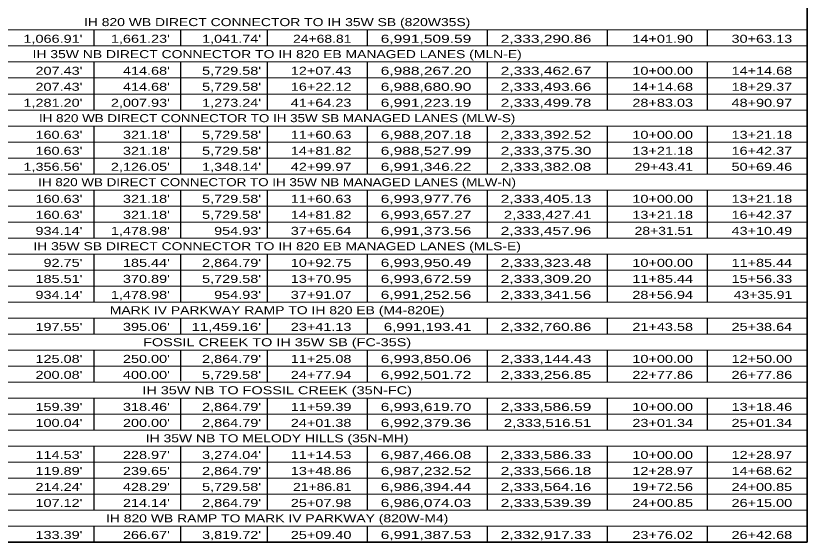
# Model space of a CAD drawing. Extents: x 1953053 to 1967065, y 7363860 to 7371201.
# Drawn here: x 1954423 to 1955610, y 7367776 to 7368565 of the extents above; entities that cross this region are included whole.
import ezdxf
from ezdxf.enums import TextEntityAlignment as Align

# ---------------------------------------------------------------- set-up
doc = ezdxf.new("R2010")
doc.units = 0
doc.header["$LTSCALE"] = 4.8
doc.layers.add('10', color=7, linetype='Continuous')
doc.layers.add('12', color=7, linetype='Continuous', lineweight=25)

msp = doc.modelspace()

# ---------------------------------------------------------------- linework, layer by layer
at = {"layer": '12', "lineweight": 35}
for p, q in [((1955609.815, 7367775.748), (1955609.815, 7370055.746)), ((1953886.483, 7367775.748), (1955609.815, 7367775.748))]:
    msp.add_line(p, q, dxfattribs=at)
at = {"layer": '12', "lineweight": 13}
for p, q in [((1953886.483, 7368543.748), (1955609.815, 7368543.748)), ((1953886.483, 7368519.748), (1955609.815, 7368519.748)), ((1953886.483, 7368495.748), (1955609.815, 7368495.748)), ((1953886.483, 7368471.748), (1955609.815, 7368471.748)), ((1953886.483, 7368447.748), (1955609.815, 7368447.748)), ((1953886.483, 7368423.748), (1955609.815, 7368423.748)), ((1953886.483, 7368399.748), (1955609.815, 7368399.748)), ((1953886.483, 7368375.748), (1955609.815, 7368375.748)), ((1953886.483, 7368351.748), (1955609.815, 7368351.748)), ((1953886.483, 7368327.748), (1955609.815, 7368327.748)), ((1953886.483, 7368303.748), (1955609.815, 7368303.748)), ((1953886.483, 7368279.748), (1955609.815, 7368279.748)), ((1953886.483, 7368255.748), (1955609.815, 7368255.748)), ((1953886.483, 7368231.748), (1955609.815, 7368231.748)), ((1953886.483, 7368207.748), (1955609.815, 7368207.748)), ((1953886.483, 7368183.748), (1955609.815, 7368183.748)), ((1953886.483, 7368159.748), (1955609.815, 7368159.748)), ((1953886.483, 7368135.748), (1955609.815, 7368135.748)), ((1953886.483, 7368111.748), (1955609.815, 7368111.748)), ((1953886.483, 7368087.748), (1955609.815, 7368087.748)), ((1953886.483, 7368063.748), (1955609.815, 7368063.748)), ((1953886.483, 7368039.748), (1955609.815, 7368039.748)), ((1953886.483, 7368015.748), (1955609.815, 7368015.748)), ((1953886.483, 7367991.748), (1955609.815, 7367991.748)), ((1953886.483, 7367967.748), (1955609.815, 7367967.748)), ((1953886.483, 7367943.748), (1955609.815, 7367943.748)), ((1953886.483, 7367919.748), (1955609.815, 7367919.748)), ((1953886.483, 7367895.748), (1955609.815, 7367895.748)), ((1953886.483, 7367871.748), (1955609.815, 7367871.748)), ((1953886.483, 7367847.748), (1955609.815, 7367847.748)), ((1953886.483, 7367823.748), (1955609.815, 7367823.748)), ((1953886.483, 7367823.748), (1955609.815, 7367823.748)), ((1953886.483, 7367799.748), (1955609.815, 7367799.748))]:
    msp.add_line(p, q, dxfattribs=at)
at = {"layer": '12'}
for p, q in [((1954539.815, 7368543.748), (1954539.815, 7368519.748)), ((1954669.815, 7368543.748), (1954669.815, 7368519.748)), ((1954799.815, 7368543.748), (1954799.815, 7368519.748)), ((1954949.815, 7368543.748), (1954949.815, 7368519.748)), ((1955129.815, 7368543.748), (1955129.815, 7368519.748)), ((1955309.815, 7368543.748), (1955309.815, 7368519.748)), ((1955459.815, 7368543.748), (1955459.815, 7368519.748)), ((1954539.815, 7368495.748), (1954539.815, 7368423.748)), ((1954669.815, 7368495.748), (1954669.815, 7368423.748)), ((1954799.815, 7368495.748), (1954799.815, 7368423.748)), ((1954949.815, 7368495.748), (1954949.815, 7368423.748)), ((1955129.815, 7368495.748), (1955129.815, 7368423.748)), ((1955309.815, 7368495.748), (1955309.815, 7368423.748)), ((1955459.815, 7368495.748), (1955459.815, 7368423.748)), ((1954539.815, 7368399.748), (1954539.815, 7368327.748)), ((1954669.815, 7368399.748), (1954669.815, 7368327.748)), ((1954799.815, 7368399.748), (1954799.815, 7368327.748)), ((1954949.815, 7368399.748), (1954949.815, 7368327.748)), ((1955129.815, 7368399.748), (1955129.815, 7368327.748)), ((1955309.815, 7368399.748), (1955309.815, 7368327.748)), ((1955459.815, 7368399.748), (1955459.815, 7368327.748)), ((1954539.815, 7368303.748), (1954539.815, 7368231.748)), ((1954669.815, 7368303.748), (1954669.815, 7368231.748)), ((1954799.815, 7368303.748), (1954799.815, 7368231.748)), ((1954949.815, 7368303.748), (1954949.815, 7368231.748)), ((1955129.815, 7368303.748), (1955129.815, 7368231.748)), ((1955309.815, 7368303.748), (1955309.815, 7368231.748)), ((1955459.815, 7368303.748), (1955459.815, 7368231.748)), ((1954539.815, 7368207.748), (1954539.815, 7368135.748)), ((1954669.815, 7368207.748), (1954669.815, 7368135.748)), ((1954799.815, 7368207.748), (1954799.815, 7368135.748)), ((1954949.815, 7368207.748), (1954949.815, 7368135.748)), ((1955129.815, 7368207.748), (1955129.815, 7368135.748)), ((1955309.815, 7368207.748), (1955309.815, 7368135.748)), ((1955459.815, 7368207.748), (1955459.815, 7368135.748)), ((1954539.815, 7368111.748), (1954539.815, 7368087.748)), ((1954669.815, 7368111.748), (1954669.815, 7368087.748)), ((1954799.815, 7368111.748), (1954799.815, 7368087.748)), ((1954949.815, 7368111.748), (1954949.815, 7368087.748)), ((1955129.815, 7368111.748), (1955129.815, 7368087.748)), ((1955309.815, 7368111.748), (1955309.815, 7368087.748)), ((1955459.815, 7368111.748), (1955459.815, 7368087.748)), ((1954539.815, 7368063.748), (1954539.815, 7368015.748)), ((1954669.815, 7368063.748), (1954669.815, 7368017.838)), ((1954799.815, 7368063.748), (1954799.815, 7368015.748)), ((1954949.815, 7368063.748), (1954949.815, 7368015.748)), ((1955129.815, 7368063.748), (1955129.815, 7368015.748)), ((1955309.815, 7368063.748), (1955309.815, 7368015.748)), ((1955459.815, 7368063.748), (1955459.815, 7368015.748)), ((1954539.815, 7367991.748), (1954539.815, 7367943.748)), ((1954669.815, 7367991.748), (1954669.815, 7367943.748)), ((1954799.815, 7367991.748), (1954799.815, 7367943.748)), ((1954949.815, 7367991.748), (1954949.815, 7367943.748)), ((1955129.815, 7367991.748), (1955129.815, 7367943.748)), ((1955309.815, 7367991.748), (1955309.815, 7367943.748)), ((1955459.815, 7367991.748), (1955459.815, 7367943.748)), ((1954539.815, 7367919.748), (1954539.815, 7367823.748)), ((1954669.815, 7367919.748), (1954669.815, 7367823.748)), ((1954799.815, 7367919.748), (1954799.815, 7367823.748)), ((1954949.815, 7367919.748), (1954949.815, 7367823.748)), ((1955129.815, 7367919.748), (1955129.815, 7367823.748)), ((1955309.815, 7367919.748), (1955309.815, 7367823.748)), ((1955459.815, 7367919.748), (1955459.815, 7367823.748)), ((1954539.815, 7367799.748), (1954539.815, 7367775.748)), ((1954669.815, 7367799.748), (1954669.815, 7367775.748)), ((1954799.815, 7367799.748), (1954799.815, 7367775.748)), ((1954949.815, 7367799.748), (1954949.815, 7367775.748)), ((1955129.815, 7367799.748), (1955129.815, 7367775.748)), ((1955309.815, 7367799.748), (1955309.815, 7367775.748)), ((1955459.815, 7367799.748), (1955459.815, 7367775.748))]:
    msp.add_line(p, q, dxfattribs=at)

# ---------------------------------------------------------------- texts
at = {"layer": '10'}
for s, width, p in [('IH 820 WB DIRECT CONNECTOR TO IH 35W SB (820W35S)', 1.3, (1954814.815, 7368549.542)), ('IH 35W NB DIRECT CONNECTOR TO IH 820 EB MANAGED LANES (MLN-E)', 1.3, (1954814.816, 7368501.542)), ('IH 820 WB DIRECT CONNECTOR TO IH 35W SB MANAGED LANES (MLW-S)', 1.25, (1954814.816, 7368405.542)), ('IH 820 WB DIRECT CONNECTOR TO IH 35W NB MANAGED LANES (MLW-N)', 1.25, (1954814.816, 7368309.542)), ('IH 35W SB DIRECT CONNECTOR TO IH 820 EB MANAGED LANES (MLS-E)', 1.3, (1954814.816, 7368213.542)), ('MARK IV PARKWAY RAMP TO IH 820 EB (M4-820E)', 1.3, (1954814.815, 7368117.542)), ('FOSSIL CREEK TO IH 35W SB (FC-35S)', 1.35, (1954814.815, 7368069.542)), ('IH 35W NB TO FOSSIL CREEK (35N-FC)', 1.35, (1954814.815, 7367997.542)), ('IH 35W NB TO MELODY HILLS (35N-MH)', 1.3, (1954814.815, 7367925.542)), ('IH 820 WB RAMP TO MARK IV PARKWAY (820W-M4)', 1.3, (1954814.815, 7367805.542))]:
    msp.add_text(s, height=12, dxfattribs=dict(at, width=width)).set_placement(p, align=Align.CENTER)
for s, width, p in [("1,066.91'", 1.35, (1954522.742, 7368524.575)), ("1,661.23'", 1.35, (1954653.939, 7368524.575)), ("1,041.74'", 1.35, (1954790.708, 7368524.575)), ('24+68.81', 1.3, (1954926.252, 7368524.575)), ('6,991,509.59', 1.45, (1955106.017, 7368524.575)), ('2,333,290.86', 1.45, (1955286.017, 7368524.575)), ('14+01.90', 1.35, (1955438.595, 7368524.575)), ('30+63.13', 1.35, (1955587.327, 7368524.575)), ("207.43'", 1.35, (1954522.742, 7368476.577)), ("414.68'", 1.35, (1954653.939, 7368476.577)), ("5,729.58'", 1.35, (1954790.708, 7368476.577)), ('12+07.43', 1.35, (1954926.252, 7368476.577)), ('6,988,267.20', 1.45, (1955106.017, 7368476.577)), ('2,333,462.67', 1.45, (1955286.017, 7368476.577)), ('10+00.00', 1.35, (1955438.595, 7368476.577)), ('14+14.68', 1.35, (1955587.327, 7368476.577)), ("207.43'", 1.35, (1954522.742, 7368452.577)), ("414.68'", 1.35, (1954653.939, 7368452.577)), ("5,729.58'", 1.35, (1954790.708, 7368452.577)), ('16+22.12', 1.35, (1954926.252, 7368452.577)), ('6,988,680.90', 1.45, (1955106.017, 7368452.577)), ('2,333,493.66', 1.45, (1955286.017, 7368452.577)), ('14+14.68', 1.35, (1955438.595, 7368452.577)), ('18+29.37', 1.35, (1955587.327, 7368452.577)), ("1,281.20'", 1.35, (1954522.742, 7368428.577)), ("2,007.93'", 1.35, (1954653.939, 7368428.577)), ("1,273.24'", 1.35, (1954790.708, 7368428.577)), ('41+64.23', 1.35, (1954926.252, 7368428.577)), ('6,991,223.19', 1.45, (1955106.017, 7368428.577)), ('2,333,499.78', 1.45, (1955286.017, 7368428.577)), ('28+83.03', 1.35, (1955438.595, 7368428.577)), ('48+90.97', 1.35, (1955587.327, 7368428.577)), ("160.63'", 1.35, (1954522.742, 7368380.575)), ("321.18'", 1.35, (1954653.939, 7368380.575)), ("5,729.58'", 1.35, (1954790.708, 7368380.575)), ('11+60.63', 1.35, (1954926.252, 7368380.575)), ('6,988,207.18', 1.45, (1955106.017, 7368380.575)), ('2,333,392.52', 1.45, (1955286.017, 7368380.575)), ('10+00.00', 1.35, (1955438.595, 7368380.575)), ('13+21.18', 1.35, (1955587.327, 7368380.575)), ("160.63'", 1.35, (1954522.742, 7368356.575)), ("321.18'", 1.35, (1954653.939, 7368356.575)), ("5,729.58'", 1.35, (1954790.708, 7368356.575)), ('14+81.82', 1.35, (1954926.252, 7368356.575)), ('6,988,527.99', 1.45, (1955106.017, 7368356.575)), ('2,333,375.30', 1.45, (1955286.017, 7368356.575)), ('13+21.18', 1.35, (1955438.595, 7368356.575)), ('16+42.37', 1.35, (1955587.327, 7368356.575)), ("1,356.56'", 1.35, (1954522.742, 7368332.577)), ("2,126.05'", 1.35, (1954653.939, 7368332.577)), ("1,348.14'", 1.35, (1954790.708, 7368332.577)), ('42+99.97', 1.35, (1954926.252, 7368332.577)), ('6,991,346.22', 1.45, (1955106.017, 7368332.577)), ('2,333,382.08', 1.45, (1955286.017, 7368332.577)), ('29+43.41', 1.3, (1955438.595, 7368332.577)), ('50+69.46', 1.35, (1955587.327, 7368332.577)), ("160.63'", 1.35, (1954522.742, 7368284.577)), ("321.18'", 1.35, (1954653.939, 7368284.577)), ("5,729.58'", 1.35, (1954790.708, 7368284.577)), ('11+60.63', 1.35, (1954926.252, 7368284.577)), ('6,993,977.76', 1.45, (1955106.017, 7368284.577)), ('2,333,405.13', 1.45, (1955286.017, 7368284.577)), ('10+00.00', 1.35, (1955438.595, 7368284.577)), ('13+21.18', 1.35, (1955587.327, 7368284.577)), ("160.63'", 1.35, (1954522.742, 7368260.577)), ("321.18'", 1.35, (1954653.939, 7368260.577)), ("5,729.58'", 1.35, (1954790.708, 7368260.577)), ('14+81.82', 1.35, (1954926.252, 7368260.577)), ('6,993,657.27', 1.45, (1955106.017, 7368260.577)), ('2,333,427.41', 1.4, (1955286.017, 7368260.577)), ('13+21.18', 1.35, (1955438.595, 7368260.577)), ('16+42.37', 1.35, (1955587.327, 7368260.577)), ("934.14'", 1.35, (1954522.742, 7368236.577)), ("1,478.98'", 1.35, (1954653.939, 7368236.577)), ("954.93'", 1.35, (1954790.708, 7368236.577)), ('37+65.64', 1.35, (1954926.252, 7368236.577)), ('6,991,373.56', 1.45, (1955106.017, 7368236.577)), ('2,333,457.96', 1.45, (1955286.017, 7368236.577)), ('28+31.51', 1.3, (1955438.595, 7368236.577)), ('43+10.49', 1.35, (1955587.327, 7368236.577)), ("92.75'", 1.35, (1954522.742, 7368188.577)), ("185.44'", 1.35, (1954653.939, 7368188.577)), ("2,864.79'", 1.35, (1954790.708, 7368188.577)), ('10+92.75', 1.35, (1954926.252, 7368188.577)), ('6,993,950.49', 1.45, (1955106.017, 7368188.577)), ('2,333,323.48', 1.45, (1955286.017, 7368188.577)), ('10+00.00', 1.35, (1955438.595, 7368188.577)), ('11+85.44', 1.35, (1955587.327, 7368188.577)), ("185.51'", 1.35, (1954522.742, 7368164.577)), ("370.89'", 1.35, (1954653.939, 7368164.577)), ("5,729.58'", 1.35, (1954790.708, 7368164.577)), ('13+70.95', 1.35, (1954926.252, 7368164.577)), ('6,993,672.59', 1.45, (1955106.017, 7368164.577)), ('2,333,309.20', 1.45, (1955286.017, 7368164.577)), ('11+85.44', 1.35, (1955438.595, 7368164.577)), ('15+56.33', 1.35, (1955587.327, 7368164.577)), ("934.14'", 1.35, (1954522.742, 7368140.577)), ("1,478.98'", 1.35, (1954653.939, 7368140.577)), ("954.93'", 1.35, (1954790.708, 7368140.577)), ('37+91.07', 1.35, (1954926.252, 7368140.577)), ('6,991,252.56', 1.45, (1955106.017, 7368140.577)), ('2,333,341.56', 1.45, (1955286.017, 7368140.577)), ('28+56.94', 1.35, (1955438.595, 7368140.577)), ('43+35.91', 1.3, (1955587.327, 7368140.577)), ("197.55'", 1.35, (1954522.742, 7368092.577)), ("395.06'", 1.35, (1954653.939, 7368092.577)), ("11,459.16'", 1.4, (1954790.708, 7368092.577)), ('23+41.13', 1.35, (1954926.252, 7368092.577)), ('6,991,193.41', 1.4, (1955106.017, 7368092.577)), ('2,332,760.86', 1.45, (1955286.017, 7368092.577)), ('21+43.58', 1.35, (1955438.595, 7368092.577)), ('25+38.64', 1.35, (1955587.327, 7368092.577)), ("125.08'", 1.35, (1954522.742, 7368044.577)), ("250.00'", 1.35, (1954653.939, 7368044.577)), ("2,864.79'", 1.35, (1954790.708, 7368044.577)), ('11+25.08', 1.35, (1954926.252, 7368044.577)), ('6,993,850.06', 1.45, (1955106.017, 7368044.577)), ('2,333,144.43', 1.45, (1955286.017, 7368044.577)), ('10+00.00', 1.35, (1955438.595, 7368044.577)), ('12+50.00', 1.35, (1955587.327, 7368044.577)), ("200.08'", 1.35, (1954522.742, 7368020.577)), ("400.00'", 1.35, (1954653.939, 7368020.577)), ("5,729.58'", 1.35, (1954790.708, 7368020.577)), ('24+77.94', 1.35, (1954926.252, 7368020.577)), ('6,992,501.72', 1.45, (1955106.017, 7368020.577)), ('2,333,256.85', 1.45, (1955286.017, 7368020.577)), ('22+77.86', 1.35, (1955438.595, 7368020.577)), ('26+77.86', 1.35, (1955587.327, 7368020.577)), ("159.39'", 1.35, (1954522.742, 7367972.577)), ("318.46'", 1.35, (1954653.939, 7367972.577)), ("2,864.79'", 1.35, (1954790.708, 7367972.577)), ('11+59.39', 1.35, (1954926.252, 7367972.577)), ('6,993,619.70', 1.45, (1955106.017, 7367972.577)), ('2,333,586.59', 1.45, (1955286.017, 7367972.577)), ('10+00.00', 1.35, (1955438.595, 7367972.577)), ('13+18.46', 1.35, (1955587.327, 7367972.577)), ("100.04'", 1.35, (1954522.742, 7367948.577)), ("200.00'", 1.35, (1954653.939, 7367948.577)), ("2,864.79'", 1.35, (1954790.708, 7367948.577)), ('24+01.38', 1.35, (1954926.252, 7367948.577)), ('6,992,379.36', 1.45, (1955106.017, 7367948.577)), ('2,333,516.51', 1.4, (1955286.017, 7367948.577)), ('23+01.34', 1.35, (1955438.595, 7367948.577)), ('25+01.34', 1.35, (1955587.327, 7367948.577)), ("114.53'", 1.35, (1954522.742, 7367900.575)), ("228.97'", 1.35, (1954653.939, 7367900.575)), ("3,274.04'", 1.35, (1954790.708, 7367900.575)), ('11+14.53', 1.35, (1954926.252, 7367900.575)), ('6,987,466.08', 1.45, (1955106.017, 7367900.575)), ('2,333,586.33', 1.45, (1955286.017, 7367900.575)), ('10+00.00', 1.35, (1955438.595, 7367900.575)), ('12+28.97', 1.35, (1955587.327, 7367900.575)), ("119.89'", 1.35, (1954522.742, 7367876.575)), ("239.65'", 1.35, (1954653.939, 7367876.575)), ("2,864.79'", 1.35, (1954790.708, 7367876.575)), ('13+48.86', 1.35, (1954926.252, 7367876.575)), ('6,987,232.52', 1.45, (1955106.017, 7367876.575)), ('2,333,566.18', 1.45, (1955286.017, 7367876.575)), ('12+28.97', 1.35, (1955438.595, 7367876.575)), ('14+68.62', 1.35, (1955587.327, 7367876.575)), ("214.24'", 1.35, (1954522.742, 7367852.575)), ("428.29'", 1.35, (1954653.939, 7367852.575)), ("5,729.58'", 1.35, (1954790.708, 7367852.575)), ('21+86.81', 1.3, (1954926.252, 7367852.575)), ('6,986,394.44', 1.45, (1955106.017, 7367852.575)), ('2,333,564.16', 1.45, (1955286.017, 7367852.575)), ('19+72.56', 1.35, (1955438.595, 7367852.575)), ('24+00.85', 1.35, (1955587.327, 7367852.575)), ("107.12'", 1.35, (1954522.742, 7367828.575)), ("214.14'", 1.35, (1954653.939, 7367828.575)), ("2,864.79'", 1.35, (1954790.708, 7367828.575)), ('25+07.98', 1.35, (1954926.252, 7367828.575)), ('6,986,074.03', 1.45, (1955106.017, 7367828.575)), ('2,333,539.39', 1.45, (1955286.017, 7367828.575)), ('24+00.85', 1.35, (1955438.595, 7367828.575)), ('26+15.00', 1.35, (1955587.327, 7367828.575)), ("133.39'", 1.35, (1954522.742, 7367780.577)), ("266.67'", 1.35, (1954653.939, 7367780.577)), ("3,819.72'", 1.35, (1954790.708, 7367780.577)), ('25+09.40', 1.35, (1954926.252, 7367780.577)), ('6,991,387.53', 1.45, (1955106.017, 7367780.577)), ('2,332,917.33', 1.45, (1955286.017, 7367780.577)), ('23+76.02', 1.35, (1955438.595, 7367780.577)), ('26+42.68', 1.35, (1955587.327, 7367780.577))]:
    msp.add_text(s, height=12, dxfattribs=dict(at, width=width)).set_placement(p, align=Align.RIGHT)

doc.saveas('drawing.dxf')
